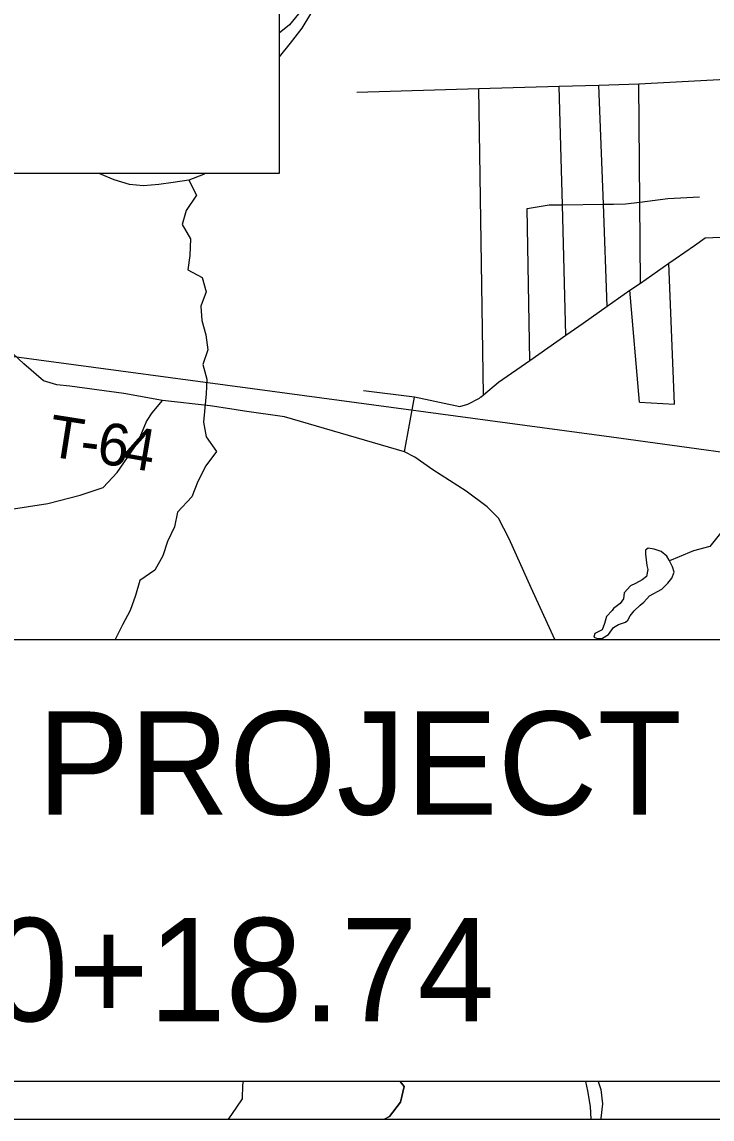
# Model space of a CAD drawing. Extents: x -37878.7 to -37844.7, y -19791.4 to -19769.4.
# Drawn here: x -37874.132 to -37873.196, y -19777.385 to -19775.898 of the extents above; entities that cross this region are included whole.
import ezdxf

# ---------------------------------------------------------------- set-up
doc = ezdxf.new("R2010")
doc.units = 0
for name, color, linetype in [('GM_X_City_Street', 7, 'Continuous'), ('GM_X_County_Road', 7, 'Continuous'), ('GM_X_Major_Lake', 7, 'Continuous'), ('GM_X_Major_River', 7, 'Continuous'), ('GM_X_Minor_Lake', 7, 'Continuous'), ('GM_X_Minor_River', 7, 'Continuous'), ('GM_X_Rail_Line', 7, 'Continuous'), ('GM_X_Township_Road', 7, 'Continuous'), ('GM_X_Township_Road_Text', 7, 'Continuous'), ('SH_Data', 7, 'Continuous'), ('TX_P_1', 7, 'Continuous')]:
    doc.layers.add(name, color=color, linetype=linetype)

msp = doc.modelspace()

# ---------------------------------------------------------------- linework, layer by layer
at = {"layer": 'GM_X_City_Street'}
for points in [[(-37873.5126, -19775.9884), (-37873.5125, -19775.9884), (-37873.4035, -19775.9852), (-37873.35, -19775.9836), (-37873.2955, -19775.982), (-37873.1528, -19775.9743), (-37873.1509, -19775.9741), (-37873.0942, -19775.9697), (-37873.0934, -19775.9698), (-37873.0862, -19775.9705), (-37873.086, -19775.9705)], [(-37873.4013, -19776.067), (-37873.4035, -19775.9852)], [(-37873.3384, -19776.2833), (-37873.3437, -19776.1452), (-37873.35, -19775.9836)], [(-37873.2935, -19776.252), (-37873.2943, -19776.1423), (-37873.2955, -19775.982)], [(-37873.678, -19775.9933), (-37873.5126, -19775.9884)], [(-37873.5064, -19776.4036), (-37873.5125, -19775.9884)], [(-37873.3945, -19776.3225), (-37873.3992, -19776.1459), (-37873.4013, -19776.067), (-37873.4013, -19776.067)], [(-37873.4472, -19776.1511), (-37873.4171, -19776.1461), (-37873.3992, -19776.1459), (-37873.3437, -19776.1452), (-37873.3303, -19776.145)], [(-37873.3303, -19776.145), (-37873.33, -19776.145), (-37873.3136, -19776.1448), (-37873.2943, -19776.1423), (-37873.2562, -19776.1373), (-37873.2134, -19776.1353)], [(-37873.4434, -19776.3568), (-37873.4472, -19776.1511)], [(-37873.5099, -19776.4065), (-37873.5096, -19776.4063), (-37873.5064, -19776.4036), (-37873.486, -19776.3865), (-37873.4434, -19776.3568), (-37873.3945, -19776.3225), (-37873.3712, -19776.3063), (-37873.3384, -19776.2833), (-37873.3077, -19776.2619), (-37873.2935, -19776.252), (-37873.2548, -19776.225), (-37873.2466, -19776.2192), (-37873.2203, -19776.201), (-37873.2057, -19776.1908), (-37873.1641, -19776.1888)], [(-37873.2471, -19776.4163), (-37873.2548, -19776.225)], [(-37873.2947, -19776.4136), (-37873.3077, -19776.2619)], [(-37873.6, -19776.4068), (-37873.669, -19776.398)], [(-37873.6133, -19776.4809), (-37873.6, -19776.4068), (-37873.5999, -19776.4062), (-37873.5382, -19776.4196), (-37873.5276, -19776.4162), (-37873.5119, -19776.4082), (-37873.5099, -19776.4065)], [(-37873.2947, -19776.4136), (-37873.2471, -19776.4163)], [(-37873.4096, -19776.7352), (-37873.4416, -19776.6652), (-37873.4713, -19776.5987), (-37873.486, -19776.5709), (-37873.5011, -19776.5553), (-37873.5297, -19776.534), (-37873.5751, -19776.5051), (-37873.5994, -19776.4882), (-37873.6133, -19776.4809), (-37873.7759, -19776.4336), (-37873.8305, -19776.4255), (-37873.8503, -19776.4225)]]:
    msp.add_lwpolyline(points, dxfattribs=at)
at = {"layer": 'GM_X_County_Road'}
for points in [[(-37874.639, -19776.5947), (-37874.3604, -19776.5921), (-37874.303, -19776.5835), (-37874.1818, -19776.5638), (-37874.0968, -19776.5507), (-37874.0531, -19776.5394), (-37874.0219, -19776.5292), (-37874.003, -19776.509), (-37873.9748, -19776.4684), (-37873.963, -19776.4396), (-37873.9553, -19776.4281), (-37873.9413, -19776.4114)], [(-37873.8503, -19776.4225), (-37873.8767, -19776.4186), (-37873.9413, -19776.4114)]]:
    msp.add_lwpolyline(points, dxfattribs=at)
at = {"layer": 'GM_X_Major_Lake'}
for points in [[(-37873.8521, -19777.3854), (-37873.8475, -19777.379), (-37873.8328, -19777.3582), (-37873.8325, -19777.3388), (-37873.8318, -19777.3343)], [(-37873.6192, -19777.3343), (-37873.6138, -19777.3413), (-37873.6187, -19777.3623), (-37873.6338, -19777.382), (-37873.6406, -19777.3854)], [(-37873.6406, -19777.3854), (-37873.6338, -19777.382), (-37873.6187, -19777.3623), (-37873.6138, -19777.3413), (-37873.6192, -19777.3343)]]:
    msp.add_lwpolyline(points, dxfattribs=at)
at = {"layer": 'GM_X_Major_River'}
for points in [[(-37873.753, -19775.8819), (-37873.7693, -19775.902), (-37873.7835, -19775.9134)], [(-37873.7408, -19775.887), (-37873.7525, -19775.9066), (-37873.7684, -19775.9267), (-37873.7835, -19775.9454)], [(-37873.8838, -19776.1036), (-37873.8859, -19776.1049), (-37873.9058, -19776.1125), (-37873.927, -19776.1157), (-37873.9466, -19776.1184), (-37873.9674, -19776.1203), (-37873.9864, -19776.1185), (-37874.007, -19776.1121), (-37874.0265, -19776.1041), (-37874.0279, -19776.1036)], [(-37873.3603, -19777.3854), (-37873.3613, -19777.3686), (-37873.3648, -19777.347), (-37873.3675, -19777.3343)], [(-37873.3603, -19777.3854), (-37873.3613, -19777.3686), (-37873.3648, -19777.347), (-37873.3675, -19777.3343)], [(-37873.3506, -19777.3343), (-37873.347, -19777.3455), (-37873.3451, -19777.3648), (-37873.3474, -19777.3842), (-37873.3474, -19777.3854)], [(-37873.3506, -19777.3343), (-37873.347, -19777.3455), (-37873.3451, -19777.3648), (-37873.3474, -19777.3842), (-37873.3474, -19777.3854)]]:
    msp.add_lwpolyline(points, dxfattribs=at)
at = {"layer": 'GM_X_Minor_Lake'}
msp.add_line((-37873.2868, -19776.6196), (-37873.2849, -19776.6351), dxfattribs=at)
msp.add_lwpolyline([(-37873.2849, -19776.6351), (-37873.2833, -19776.6404), (-37873.2854, -19776.6499), (-37873.291, -19776.6546), (-37873.3, -19776.6594), (-37873.3071, -19776.6626), (-37873.3156, -19776.6718), (-37873.3166, -19776.6802), (-37873.321, -19776.6864), (-37873.3299, -19776.6934), (-37873.3318, -19776.6961), (-37873.3396, -19776.7042), (-37873.3424, -19776.7134), (-37873.3452, -19776.7222), (-37873.3554, -19776.727), (-37873.3568, -19776.7323), (-37873.3518, -19776.7341), (-37873.345, -19776.7336), (-37873.3368, -19776.7285), (-37873.3302, -19776.7192), (-37873.3234, -19776.7149), (-37873.3136, -19776.7117), (-37873.3107, -19776.7089), (-37873.3074, -19776.7032), (-37873.3022, -19776.6966), (-37873.294, -19776.6885), (-37873.2888, -19776.6846), (-37873.281, -19776.676), (-37873.2646, -19776.667), (-37873.2564, -19776.6588), (-37873.2509, -19776.6522), (-37873.2476, -19776.6442), (-37873.25, -19776.6367), (-37873.2544, -19776.6276), (-37873.2579, -19776.6224), (-37873.2653, -19776.6161), (-37873.2748, -19776.6129), (-37873.2832, -19776.6116), (-37873.2865, -19776.6143), (-37873.2868, -19776.6196)], dxfattribs=at)
at = {"layer": 'GM_X_Minor_River'}
for points in [[(-37873.9058, -19776.1125), (-37873.8952, -19776.1328), (-37873.9095, -19776.1536), (-37873.9148, -19776.1727), (-37873.9034, -19776.1922), (-37873.9044, -19776.2146), (-37873.907, -19776.234), (-37873.8879, -19776.2446), (-37873.8822, -19776.2638), (-37873.8893, -19776.2834), (-37873.8882, -19776.3027), (-37873.8828, -19776.3223), (-37873.8798, -19776.3427), (-37873.8869, -19776.3626), (-37873.8812, -19776.3822), (-37873.8823, -19776.402), (-37873.8842, -19776.421), (-37873.886, -19776.4408), (-37873.8822, -19776.4604), (-37873.8682, -19776.4803), (-37873.8829, -19776.4996), (-37873.8935, -19776.521), (-37873.9017, -19776.5417), (-37873.921, -19776.5626), (-37873.9251, -19776.5824), (-37873.9346, -19776.6024), (-37873.941, -19776.6219), (-37873.9519, -19776.6411), (-37873.9721, -19776.6552), (-37873.9781, -19776.6758), (-37873.9853, -19776.6961), (-37873.9959, -19776.7153), (-37874.0053, -19776.7345), (-37874.0055, -19776.7352)], [(-37873.0453, -19776.6076), (-37873.0659, -19776.6027), (-37873.0849, -19776.5974), (-37873.1044, -19776.5888), (-37873.1247, -19776.5801), (-37873.1445, -19776.5775), (-37873.1641, -19776.5817), (-37873.1832, -19776.5889), (-37873.1995, -19776.6094), (-37873.2217, -19776.6152), (-37873.2412, -19776.6232), (-37873.2539, -19776.6287)]]:
    msp.add_lwpolyline(points, dxfattribs=at)
at = {"layer": 'GM_X_Rail_Line'}
msp.add_lwpolyline([(-37872.5548, -19776.5667), (-37872.7322, -19776.5426), (-37872.8542, -19776.5262), (-37873.063, -19776.4978), (-37873.3325, -19776.4609), (-37873.8193, -19776.3953), (-37874.1091, -19776.3564), (-37874.7711, -19776.2673)], dxfattribs=at)
at = {"layer": 'GM_X_Township_Road'}
msp.add_lwpolyline([(-37873.9413, -19776.4114), (-37873.9939, -19776.4017), (-37874.0673, -19776.392), (-37874.0848, -19776.3898), (-37874.1027, -19776.3845), (-37874.1294, -19776.3616), (-37874.1597, -19776.3331), (-37874.1902, -19776.2944), (-37874.2239, -19776.2637), (-37874.2392, -19776.2458), (-37874.256, -19776.239), (-37874.3555, -19776.2019), (-37874.5429, -19776.1172), (-37874.5586, -19776.1119), (-37874.5666, -19776.1132), (-37874.5732, -19776.1148), (-37874.5819, -19776.1189), (-37874.5992, -19776.127), (-37874.6494, -19776.1658), (-37874.7129, -19776.225)], dxfattribs=at)
at = {"layer": 'SH_Data'}
msp.add_line((-37876.1504, -19777.3854), (-37869.1504, -19777.3854), dxfattribs=at)
at = {"layer": 'TX_P_1'}
for p, q in [((-37873.7835, -19775.5045), (-37873.7835, -19776.1036)), ((-37873.7835, -19776.1036), (-37875.7623, -19776.1036)), ((-37874.7897, -19776.7352), (-37873.0316, -19776.7352)), ((-37873.0316, -19777.3343), (-37874.7897, -19777.3343))]:
    msp.add_line(p, q, dxfattribs=at)

# ---------------------------------------------------------------- texts
at = {"layer": 'GM_X_Township_Road_Text'}
for s, rotation, p in [('T', 351.0583, (-37874.099, -19776.4863)), ('6', 351.7705, (-37874.0322, -19776.496)), ('4', 350.3161, (-37873.9979, -19776.5009)), ('-', 352.9071, (-37874.055, -19776.4931))]:
    msp.add_text(s, height=0.0568, rotation=rotation, dxfattribs=at).set_placement(p)
at = {"layer": 'TX_P_1'}
for s, p in [('BEGIN PROJECT', (-37874.7457, -19776.9728)), ('STA. 10+18.74', (-37874.7457, -19777.2528))]:
    msp.add_text(s, height=0.14, rotation=360, dxfattribs=at).set_placement(p)

doc.saveas('drawing.dxf')
